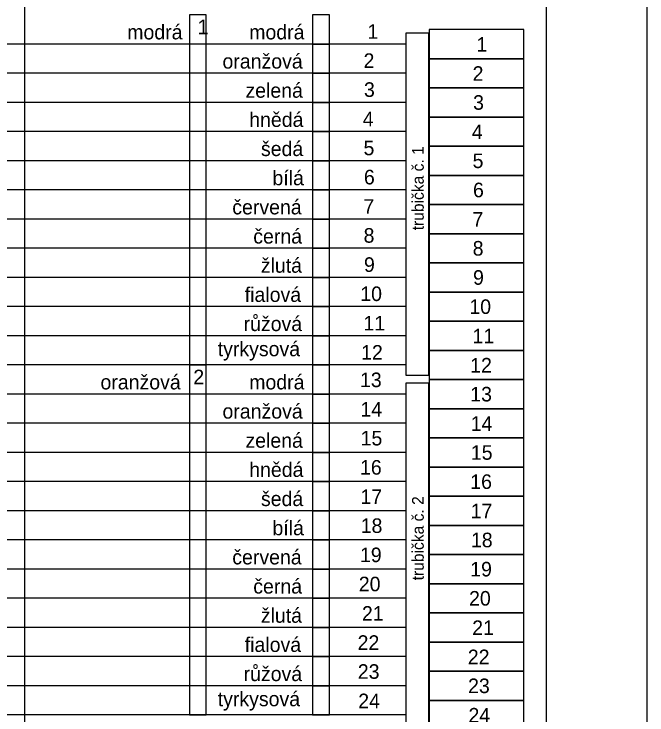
# Model space of a CAD drawing. Extents: x 1901 to 2519, y -3585 to -3154.
# Drawn here: x 2439.8 to 2516.2, y -3287.5 to -3202.9 of the extents above; entities that cross this region are included whole.
import ezdxf

# ---------------------------------------------------------------- set-up
doc = ezdxf.new("R2010")
doc.units = 0
doc.layers.add('rozvláknění', color=7, linetype='Continuous')
doc.layers.add('Vrstva 4', color=7, linetype='Continuous')

msp = doc.modelspace()

# ---------------------------------------------------------------- linework, layer by layer
at = {"layer": 'rozvláknění'}
for p, q in [((2487.131, -3206.524), (2392.43, -3206.525)), ((2489.935, -3206.524), (2489.918, -3206.524)), ((2487.131, -3210.042), (2392.43, -3210.043)), ((2489.935, -3210.044), (2489.918, -3210.044)), ((2487.131, -3213.56), (2392.43, -3213.561)), ((2487.131, -3213.564), (2487.131, -3217.084)), ((2489.935, -3213.564), (2489.918, -3213.564)), ((2487.131, -3217.078), (2392.43, -3217.079)), ((2489.935, -3217.084), (2489.918, -3217.084)), ((2487.131, -3220.596), (2392.43, -3220.598)), ((2489.935, -3220.604), (2489.918, -3220.604)), ((2487.131, -3224.115), (2392.43, -3224.116)), ((2487.131, -3224.124), (2487.131, -3227.644)), ((2489.935, -3224.124), (2489.918, -3224.124)), ((2487.131, -3227.633), (2392.43, -3227.634)), ((2489.935, -3227.644), (2489.918, -3227.644)), ((2487.131, -3231.151), (2392.43, -3231.152)), ((2489.935, -3231.164), (2489.918, -3231.164)), ((2487.131, -3234.669), (2392.43, -3234.67)), ((2487.131, -3234.684), (2487.131, -3238.204)), ((2489.935, -3234.684), (2489.918, -3234.684)), ((2487.131, -3238.187), (2392.43, -3238.189)), ((2489.935, -3238.204), (2489.918, -3238.204)), ((2487.131, -3241.706), (2392.43, -3241.707)), ((2489.935, -3241.724), (2489.918, -3241.724)), ((2487.131, -3245.224), (2392.43, -3245.225)), ((2489.935, -3245.244), (2489.918, -3245.244)), ((2487.131, -3248.764), (2392.43, -3248.765)), ((2489.935, -3248.764), (2489.918, -3248.764)), ((2487.131, -3252.282), (2392.43, -3252.283)), ((2489.935, -3252.284), (2489.918, -3252.284)), ((2487.131, -3255.8), (2392.43, -3255.801)), ((2487.131, -3255.804), (2487.131, -3259.324)), ((2489.935, -3255.804), (2489.918, -3255.804)), ((2487.131, -3259.318), (2392.43, -3259.319)), ((2489.935, -3259.324), (2489.918, -3259.324)), ((2487.131, -3262.836), (2392.43, -3262.838)), ((2489.935, -3262.844), (2489.918, -3262.844)), ((2487.131, -3266.355), (2392.43, -3266.356)), ((2487.131, -3266.364), (2487.131, -3269.884)), ((2489.935, -3266.364), (2489.918, -3266.364)), ((2487.131, -3269.873), (2392.43, -3269.874)), ((2489.935, -3269.884), (2489.918, -3269.884)), ((2487.131, -3273.391), (2392.43, -3273.392)), ((2489.935, -3273.404), (2489.918, -3273.404)), ((2487.131, -3276.909), (2392.43, -3276.91)), ((2487.131, -3276.924), (2487.131, -3280.444)), ((2489.935, -3276.924), (2489.918, -3276.924)), ((2487.131, -3280.427), (2392.43, -3280.429)), ((2489.935, -3280.444), (2489.918, -3280.444)), ((2487.131, -3283.946), (2392.43, -3283.947)), ((2489.935, -3283.964), (2489.918, -3283.964)), ((2487.131, -3287.464), (2392.43, -3287.465))]:
    msp.add_line(p, q, dxfattribs=at)
for points in [[(2504.11, -3178.544), (2441.124, -3178.543), (2441.124, -3379.277), (2504.11, -3379.277)], [(2461, -3245.226), (2463.041, -3245.226), (2463.041, -3203.007), (2461, -3203.007)], [(2477.919, -3203.007), (2475.878, -3203.007), (2475.878, -3206.526), (2477.919, -3206.526)], [(2501.378, -3204.764), (2489.935, -3204.764), (2489.935, -3208.284), (2501.378, -3208.284)], [(2489.918, -3205.198), (2487.131, -3205.198), (2487.131, -3246.458), (2489.918, -3246.458)], [(2477.919, -3206.526), (2475.878, -3206.526), (2475.878, -3210.044), (2477.919, -3210.044)], [(2501.378, -3208.284), (2489.935, -3208.284), (2489.935, -3211.804), (2501.378, -3211.804)], [(2477.919, -3210.044), (2475.878, -3210.044), (2475.878, -3213.562), (2477.919, -3213.562)], [(2501.378, -3211.804), (2489.935, -3211.804), (2489.935, -3215.324), (2501.378, -3215.324)], [(2477.919, -3213.562), (2475.878, -3213.562), (2475.878, -3217.08), (2477.919, -3217.08)], [(2501.378, -3215.324), (2489.935, -3215.324), (2489.935, -3218.844), (2501.378, -3218.844)], [(2477.919, -3217.08), (2475.878, -3217.08), (2475.878, -3220.598), (2477.919, -3220.598)], [(2501.378, -3218.844), (2489.935, -3218.844), (2489.935, -3222.364), (2501.378, -3222.364)], [(2477.919, -3220.598), (2475.878, -3220.598), (2475.878, -3224.117), (2477.919, -3224.117)], [(2501.378, -3222.364), (2489.935, -3222.364), (2489.935, -3225.884), (2501.378, -3225.884)], [(2477.919, -3224.117), (2475.878, -3224.117), (2475.878, -3227.635), (2477.919, -3227.635)], [(2501.378, -3225.884), (2489.935, -3225.884), (2489.935, -3229.404), (2501.378, -3229.404)], [(2477.919, -3227.635), (2475.878, -3227.635), (2475.878, -3231.153), (2477.919, -3231.153)], [(2501.378, -3229.404), (2489.935, -3229.404), (2489.935, -3232.924), (2501.378, -3232.924)], [(2477.919, -3231.153), (2475.878, -3231.153), (2475.878, -3234.671), (2477.919, -3234.671)], [(2501.378, -3232.924), (2489.935, -3232.924), (2489.935, -3236.444), (2501.378, -3236.444)], [(2477.919, -3234.671), (2475.878, -3234.671), (2475.878, -3238.189), (2477.919, -3238.189)], [(2501.378, -3236.444), (2489.935, -3236.444), (2489.935, -3239.964), (2501.378, -3239.964)], [(2477.919, -3238.189), (2475.878, -3238.189), (2475.878, -3241.708), (2477.919, -3241.708)], [(2501.378, -3239.964), (2489.935, -3239.964), (2489.935, -3243.484), (2501.378, -3243.484)], [(2477.919, -3241.708), (2475.878, -3241.708), (2475.878, -3245.226), (2477.919, -3245.226)], [(2501.378, -3243.484), (2489.935, -3243.484), (2489.935, -3247.004), (2501.378, -3247.004)], [(2461, -3287.466), (2463.041, -3287.466), (2463.041, -3245.247), (2461, -3245.247)], [(2477.919, -3245.247), (2475.878, -3245.247), (2475.878, -3248.766), (2477.919, -3248.766)], [(2489.918, -3247.438), (2487.131, -3247.438), (2487.131, -3288.698), (2489.918, -3288.698)], [(2501.378, -3247.004), (2489.935, -3247.004), (2489.935, -3250.524), (2501.378, -3250.524)], [(2477.919, -3248.766), (2475.878, -3248.766), (2475.878, -3252.284), (2477.919, -3252.284)], [(2501.378, -3250.524), (2489.935, -3250.524), (2489.935, -3254.044), (2501.378, -3254.044)], [(2477.919, -3252.284), (2475.878, -3252.284), (2475.878, -3255.802), (2477.919, -3255.802)], [(2501.378, -3254.044), (2489.935, -3254.044), (2489.935, -3257.564), (2501.378, -3257.564)], [(2477.919, -3255.802), (2475.878, -3255.802), (2475.878, -3259.32), (2477.919, -3259.32)], [(2501.378, -3257.564), (2489.935, -3257.564), (2489.935, -3261.084), (2501.378, -3261.084)], [(2477.919, -3259.32), (2475.878, -3259.32), (2475.878, -3262.838), (2477.919, -3262.838)], [(2501.378, -3261.084), (2489.935, -3261.084), (2489.935, -3264.604), (2501.378, -3264.604)], [(2477.919, -3262.838), (2475.878, -3262.838), (2475.878, -3266.357), (2477.919, -3266.357)], [(2501.378, -3264.604), (2489.935, -3264.604), (2489.935, -3268.124), (2501.378, -3268.124)], [(2477.919, -3266.357), (2475.878, -3266.357), (2475.878, -3269.875), (2477.919, -3269.875)], [(2501.378, -3268.124), (2489.935, -3268.124), (2489.935, -3271.644), (2501.378, -3271.644)], [(2477.919, -3269.875), (2475.878, -3269.875), (2475.878, -3273.393), (2477.919, -3273.393)], [(2501.378, -3271.644), (2489.935, -3271.644), (2489.935, -3275.164), (2501.378, -3275.164)], [(2477.919, -3273.393), (2475.878, -3273.393), (2475.878, -3276.911), (2477.919, -3276.911)], [(2501.378, -3275.164), (2489.935, -3275.164), (2489.935, -3278.684), (2501.378, -3278.684)], [(2477.919, -3276.911), (2475.878, -3276.911), (2475.878, -3280.429), (2477.919, -3280.429)], [(2501.378, -3278.684), (2489.935, -3278.684), (2489.935, -3282.204), (2501.378, -3282.204)], [(2477.919, -3280.429), (2475.878, -3280.429), (2475.878, -3283.948), (2477.919, -3283.948)], [(2501.378, -3282.204), (2489.935, -3282.204), (2489.935, -3285.724), (2501.378, -3285.724)], [(2477.919, -3283.948), (2475.878, -3283.948), (2475.878, -3287.466), (2477.919, -3287.466)], [(2501.378, -3285.724), (2489.935, -3285.724), (2489.935, -3289.244), (2501.378, -3289.244)]]:
    msp.add_lwpolyline(points, close=True, dxfattribs=at)
for points in [[(2461, -3245.226), (2463.041, -3245.226), (2463.041, -3203.007), (2461, -3203.007), (2461, -3245.226)], [(2477.919, -3203.007), (2475.878, -3203.007), (2475.878, -3206.526), (2477.919, -3206.526), (2477.919, -3203.007)], [(2477.919, -3206.526), (2475.878, -3206.526), (2475.878, -3210.044), (2477.919, -3210.044), (2477.919, -3206.526)], [(2477.919, -3210.044), (2475.878, -3210.044), (2475.878, -3213.562), (2477.919, -3213.562), (2477.919, -3210.044)], [(2477.919, -3213.562), (2475.878, -3213.562), (2475.878, -3217.08), (2477.919, -3217.08), (2477.919, -3213.562)], [(2477.919, -3217.08), (2475.878, -3217.08), (2475.878, -3220.598), (2477.919, -3220.598), (2477.919, -3217.08)], [(2477.919, -3220.598), (2475.878, -3220.598), (2475.878, -3224.117), (2477.919, -3224.117), (2477.919, -3220.598)], [(2477.919, -3224.117), (2475.878, -3224.117), (2475.878, -3227.635), (2477.919, -3227.635), (2477.919, -3224.117)], [(2477.919, -3227.635), (2475.878, -3227.635), (2475.878, -3231.153), (2477.919, -3231.153), (2477.919, -3227.635)], [(2477.919, -3231.153), (2475.878, -3231.153), (2475.878, -3234.671), (2477.919, -3234.671), (2477.919, -3231.153)], [(2477.919, -3234.671), (2475.878, -3234.671), (2475.878, -3238.189), (2477.919, -3238.189), (2477.919, -3234.671)], [(2477.919, -3238.189), (2475.878, -3238.189), (2475.878, -3241.708), (2477.919, -3241.708), (2477.919, -3238.189)], [(2477.919, -3241.708), (2475.878, -3241.708), (2475.878, -3245.226), (2477.919, -3245.226), (2477.919, -3241.708)], [(2461, -3287.466), (2463.041, -3287.466), (2463.041, -3245.247), (2461, -3245.247), (2461, -3287.466)], [(2477.919, -3245.247), (2475.878, -3245.247), (2475.878, -3248.766), (2477.919, -3248.766), (2477.919, -3245.247)], [(2477.919, -3248.766), (2475.878, -3248.766), (2475.878, -3252.284), (2477.919, -3252.284), (2477.919, -3248.766)], [(2477.919, -3252.284), (2475.878, -3252.284), (2475.878, -3255.802), (2477.919, -3255.802), (2477.919, -3252.284)], [(2477.919, -3255.802), (2475.878, -3255.802), (2475.878, -3259.32), (2477.919, -3259.32), (2477.919, -3255.802)], [(2477.919, -3259.32), (2475.878, -3259.32), (2475.878, -3262.838), (2477.919, -3262.838), (2477.919, -3259.32)], [(2477.919, -3262.838), (2475.878, -3262.838), (2475.878, -3266.357), (2477.919, -3266.357), (2477.919, -3262.838)], [(2477.919, -3266.357), (2475.878, -3266.357), (2475.878, -3269.875), (2477.919, -3269.875), (2477.919, -3266.357)], [(2477.919, -3269.875), (2475.878, -3269.875), (2475.878, -3273.393), (2477.919, -3273.393), (2477.919, -3269.875)], [(2477.919, -3273.393), (2475.878, -3273.393), (2475.878, -3276.911), (2477.919, -3276.911), (2477.919, -3273.393)], [(2477.919, -3276.911), (2475.878, -3276.911), (2475.878, -3280.429), (2477.919, -3280.429), (2477.919, -3276.911)], [(2477.919, -3280.429), (2475.878, -3280.429), (2475.878, -3283.948), (2477.919, -3283.948), (2477.919, -3280.429)], [(2477.919, -3283.948), (2475.878, -3283.948), (2475.878, -3287.466), (2477.919, -3287.466), (2477.919, -3283.948)]]:
    msp.add_lwpolyline(points, dxfattribs=at)
at = {"layer": 'Vrstva 4'}
msp.add_lwpolyline([(1901.224, -3154.468), (2516.224, -3154.468), (2516.224, -3584.968), (1901.224, -3584.968)], close=True, dxfattribs=at)

# ---------------------------------------------------------------- texts
at = {"layer": 'rozvláknění'}
for s, p in [('modrá', (2453.501, -3205.952)), ('1', (2461.995, -3205.333)), ('modrá', (2468.222, -3205.952)), ('1', (2482.49, -3205.879)), ('1', (2495.654, -3207.432)), ('oranžová', (2464.996, -3209.472)), ('2', (2482.019, -3209.399)), ('2', (2495.183, -3210.952)), ('zelená', (2467.766, -3212.992)), ('3', (2482.075, -3212.889)), ('3', (2495.238, -3214.443)), ('hnědá', (2468.224, -3216.512)), ('4', (2481.922, -3216.439)), ('4', (2495.085, -3217.992)), ('šedá', (2469.641, -3220.032)), ('5', (2482.018, -3219.929)), ('5', (2495.181, -3221.483)), ('bílá', (2471.029, -3223.552)), ('6', (2482.064, -3223.449)), ('6', (2495.227, -3225.003)), ('červená', (2466.181, -3227.072)), ('7', (2481.999, -3226.999)), ('7', (2495.163, -3228.552)), ('černá', (2468.713, -3230.592)), ('8', (2482.026, -3230.489)), ('8', (2495.189, -3232.043)), ('žlutá', (2469.621, -3234.112)), ('9', (2482.071, -3234.009)), ('9', (2495.234, -3235.563)), ('fialová', (2467.683, -3237.632)), ('10', (2481.627, -3237.529)), ('10', (2494.79, -3239.083)), ('růžová', (2467.546, -3241.152)), ('11', (2482.007, -3241.079)), ('11', (2495.171, -3242.632)), ('tyrkysová', (2464.422, -3244.184)), ('12', (2481.727, -3244.599)), ('12', (2494.891, -3246.152)), ('2', (2461.477, -3247.573)), ('oranžová', (2450.275, -3248.192)), ('modrá', (2468.222, -3248.192)), ('13', (2481.591, -3247.916)), ('13', (2494.896, -3249.643)), ('oranžová', (2464.996, -3251.712)), ('14', (2481.646, -3251.466)), ('14', (2494.951, -3253.192)), ('zelená', (2467.766, -3255.232)), ('15', (2481.666, -3254.956)), ('15', (2494.972, -3256.683)), ('16', (2481.591, -3258.476)), ('hnědá', (2468.224, -3258.752)), ('16', (2494.896, -3260.203)), ('šedá', (2469.641, -3262.272)), ('17', (2481.638, -3262.026)), ('17', (2494.943, -3263.752)), ('bílá', (2471.029, -3265.792)), ('18', (2481.677, -3265.516)), ('18', (2494.983, -3267.243)), ('červená', (2466.181, -3269.312)), ('19', (2481.588, -3269.036)), ('19', (2494.894, -3270.763)), ('černá', (2468.713, -3272.832)), ('20', (2481.449, -3272.556)), ('20', (2494.754, -3274.283)), ('žlutá', (2469.621, -3276.352)), ('21', (2481.825, -3276.106)), ('21', (2495.13, -3277.832)), ('22', (2481.301, -3279.626)), ('fialová', (2467.683, -3279.872)), ('22', (2494.606, -3281.352)), ('růžová', (2467.546, -3283.392)), ('23', (2481.329, -3283.116)), ('23', (2494.634, -3284.843)), ('tyrkysová', (2464.422, -3286.424)), ('24', (2481.379, -3286.666)), ('24', (2494.684, -3288.392))]:
    msp.add_text(s, height=1.76, dxfattribs=at).set_placement(p)
for s, p in [('trubička č. 1', (2489.286, -3228.996)), ('trubička č. 2', (2489.286, -3271.236))]:
    msp.add_text(s, height=1.408, rotation=90, dxfattribs=at).set_placement(p)

doc.saveas('drawing.dxf')
